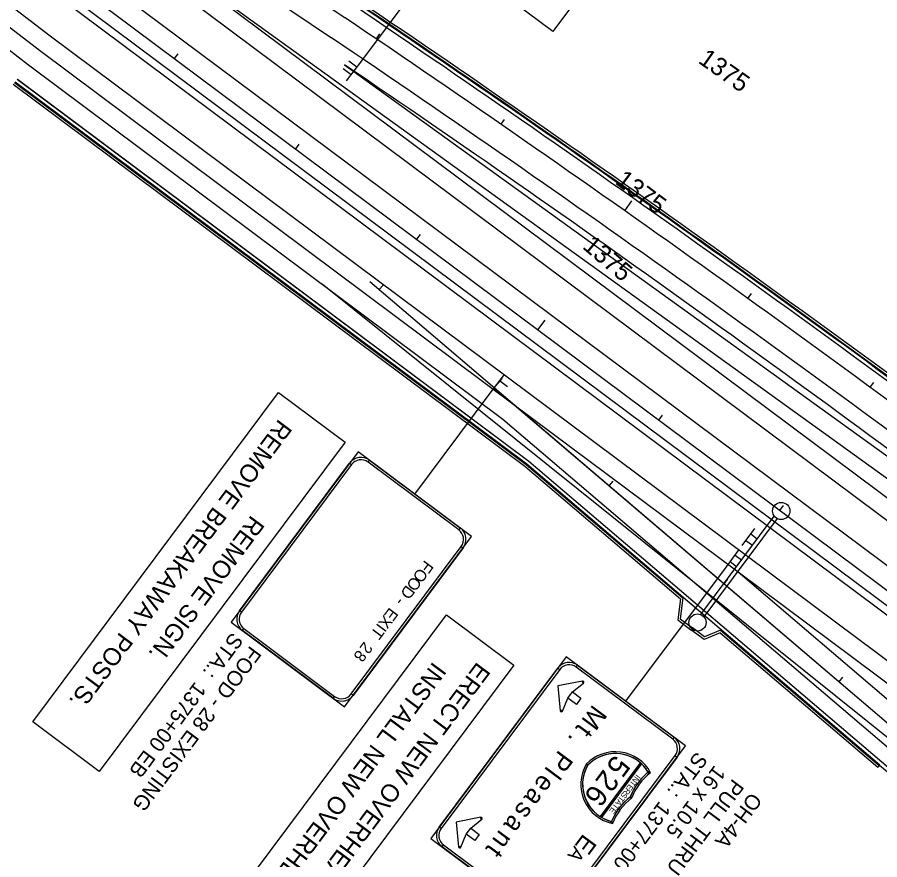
# Model space of a CAD drawing. Extents: x 2338610 to 2351914, y 366540 to 376484.
# Drawn here: x 2344129 to 2344700, y 370808 to 371366 of the extents above; entities that cross this region are included whole.
import ezdxf

# ---------------------------------------------------------------- set-up
doc = ezdxf.new("R2010")
doc.units = 0
for name, color, linetype in [('RD_HC_Cl', 7, 'Continuous'), ('RD_HC_CL_Rel', 7, 'Continuous'), ('RD_PD_Final_LnLine', 7, 'Continuous'), ('RD_PD_Final_TrvlWay', 7, 'Continuous'), ('RD_PD_MedBWall', 7, 'Continuous'), ('RD_PD_MedGR', 7, 'Continuous'), ('RD_PD_NOISE-WALL-GM', 7, 'Continuous'), ('RD_PD_PaveShd', 7, 'Continuous'), ('RD_PD_WallFill', 7, 'Continuous'), ('TR PM UNASSIGNED 3', 7, 'Continuous'), ('TR SN EXISTING - BREAK-AWAY SIGN SUPPORTS', 7, 'Continuous'), ('TR SN EXTRUDED PANEL SIGNS - GROUND MOUNTED', 7, 'Continuous'), ('TR SN EXTRUDED PANEL SIGNS- MOUNTED OVERHEAD', 7, 'Continuous'), ('TR SN UNASSIGNED 7', 7, 'Continuous')]:
    doc.layers.add(name, color=color, linetype=linetype)

msp = doc.modelspace()

# ---------------------------------------------------------------- linework, layer by layer
at = {"layer": 'RD_HC_Cl'}
for p, q in [((2339299.68, 375020.33), (2345298.75, 370542.85)), ((2343974.34, 371616.02), (2344345.74, 371365.34))]:
    msp.add_line(p, q, dxfattribs=at)
msp.add_arc((2338191.84, 362247.8), 11000, 52.99132, 55.982505, dxfattribs=at)
at = {"layer": 'RD_HC_CL_Rel'}
msp.add_line((2344362.05, 371190.8), (2344818.24, 370801.72), dxfattribs=at)
at = {"layer": 'RD_PD_Final_LnLine'}
for p, q in [((2343572.21, 371799.04), (2344150.54, 371353.45)), ((2343565.03, 371789.42), (2344143.36, 371343.83)), ((2344202.18, 371422.64), (2344782.88, 370989.22)), ((2344195, 371413.02), (2345320.98, 370572.63)), ((2344150.54, 371353.45), (2345276.52, 370513.06)), ((2344143.36, 371343.83), (2344457.72, 371109.21)), ((2344330.62, 371189.3), (2344989.66, 370660.63)), ((2344330.62, 371189.3), (2344989.66, 370660.63)), ((2344330.62, 371189.3), (2344989.66, 370660.63)), ((2344330.62, 371189.3), (2344989.66, 370660.63)), ((2344457.72, 371109.21), (2344818.24, 370801.72)), ((2344457.72, 371109.21), (2344605.78, 370998.71))]:
    msp.add_line(p, q, dxfattribs=at)
at = {"layer": 'RD_PD_Final_TrvlWay'}
for p, q in [((2343557.85, 371779.81), (2344136.19, 371334.22)), ((2343974.34, 371616.02), (2344345.74, 371365.34)), ((2343950.18, 371613.02), (2344336.79, 371352.08)), ((2344202.18, 371422.64), (2344790.37, 370998.61)), ((2344136.19, 371334.22), (2344450.23, 371099.83)), ((2344450.23, 371099.83), (2344810.46, 370792.59)), ((2344605.78, 370998.71), (2345269.34, 370503.45)), ((2344605.78, 370998.71), (2344826.03, 370810.85))]:
    msp.add_line(p, q, dxfattribs=at)
for radius in [11000, 10984]:
    msp.add_arc((2338191.84, 362247.8), radius, 52.99132, 55.982505, dxfattribs=at)
at = {"layer": 'RD_PD_MedBWall'}
for p, q in [((2344127.3, 371322.96), (2344466.02, 371070.16)), ((2344128.71, 371324.82), (2344467.41, 371072.03)), ((2344467.41, 371072.03), (2344803.97, 370784.99)), ((2344465.9, 371070.25), (2344699.6, 370870.93))]:
    msp.add_line(p, q, dxfattribs=at)
for radius in [11010, 11012.33]:
    msp.add_arc((2338191.84, 362247.8), radius, 52.99132, 55.982505, dxfattribs=at)
at = {"layer": 'RD_PD_MedGR'}
msp.add_line((2343635.7, 371774.1), (2345204.83, 370602.96), dxfattribs=at)
at = {"layer": 'RD_PD_NOISE-WALL-GM'}
for p, q in [((2344127, 371322.56), (2344465.65, 371069.81)), ((2344126.1, 371321.36), (2344464.71, 371068.64)), ((2344464.71, 371068.64), (2344567.61, 370980.88)), ((2344465.65, 371069.81), (2344569.19, 370981.5)), ((2344567.61, 370980.88), (2344565.95, 370966.87)), ((2344569.19, 370981.5), (2344567.54, 370967.55)), ((2344565.95, 370966.87), (2344574.66, 370960.37)), ((2344567.54, 370967.55), (2344575.56, 370961.57)), ((2344583.37, 370953.87), (2344574.66, 370960.37)), ((2344583.57, 370955.59), (2344575.56, 370961.57)), ((2344593.94, 370958.42), (2344583.37, 370953.87)), ((2344594.2, 370960.16), (2344583.57, 370955.59)), ((2344593.94, 370958.42), (2344698.3, 370869.41)), ((2344594.2, 370960.16), (2344699.28, 370870.55)), ((2344699.28, 370870.55), (2344698.3, 370869.41))]:
    msp.add_line(p, q, dxfattribs=at)
for radius in [11012.83, 11014.33]:
    msp.add_arc((2338191.84, 362247.8), radius, 52.99132, 55.982505, dxfattribs=at)
at = {"layer": 'RD_PD_PaveShd'}
for p, q in [((2343761.92, 371706.31), (2345306.62, 370553.4)), ((2343847.56, 371609.53), (2345290.87, 370532.3)), ((2344345.37, 371334.2), (2344797.47, 371008.28)), ((2344128.79, 371324.76), (2344467.41, 371072.03)), ((2344467.41, 371072.03), (2344803.97, 370784.99))]:
    msp.add_line(p, q, dxfattribs=at)
for radius, end in [(11010, 55.982505), (10974, 55.892847)]:
    msp.add_arc((2338191.84, 362247.8), radius, 52.99132, end, dxfattribs=at)
at = {"layer": 'RD_PD_WallFill'}
msp.add_line((2344699.49, 370870.8), (2344802.34, 370783.08), dxfattribs=at)
at = {"layer": 'TR SN EXISTING - BREAK-AWAY SIGN SUPPORTS'}
for points in [[(2344439.22, 371389.11), (2344601.89, 371607.06), (2344645.9, 371574.21), (2344483.23, 371356.26)], [(2344345.66, 371084.58), (2344182.99, 370866.63), (2344138.98, 370899.48), (2344301.65, 371117.43)]]:
    msp.add_lwpolyline(points, close=True, dxfattribs=at)
at = {"layer": 'TR SN EXTRUDED PANEL SIGNS - GROUND MOUNTED'}
for p, q in [((2344453.43, 371466.7), (2344356.55, 371336.89)), ((2344356.55, 371336.89), (2344346.45, 371323.6)), ((2344348.24, 371336.88), (2344353.53, 371332.86)), ((2344344.35, 371331.77), (2344349.66, 371327.73)), ((2344441.04, 371115.99), (2344451.14, 371129.29)), ((2344453.24, 371121.12), (2344447.93, 371125.16)), ((2344449.35, 371116), (2344444.06, 371120.02)), ((2344391.89, 371050.15), (2344441.04, 371115.99)), ((2344360.91, 371071.33), (2344361.84, 371072.58)), ((2344348.72, 371070.67), (2344349.97, 371069.74)), ((2344421.95, 371027.72), (2344421.01, 371026.47)), ((2344422.6, 371015.53), (2344423.85, 371014.6)), ((2344277.07, 370972.07), (2344275.82, 370973)), ((2344277.73, 370959.88), (2344278.66, 370961.13)), ((2344350.95, 370916.93), (2344349.7, 370917.86)), ((2344338.77, 370916.27), (2344337.83, 370915.02))]:
    msp.add_line(p, q, dxfattribs=at)
for points in [[(2344354.33, 371078.19), (2344270.22, 370965.49), (2344345.35, 370909.41), (2344429.46, 371022.11), (2344354.33, 371078.19), (2344354.33, 371078.19)], [(2344421.01, 371026.47), (2344360.91, 371071.33), (2344361.84, 371072.58), (2344421.95, 371027.72), (2344421.01, 371026.47), (2344421.01, 371026.47)], [(2344349.97, 371069.74), (2344277.07, 370972.07), (2344275.82, 370973), (2344348.72, 371070.67), (2344349.97, 371069.74), (2344349.97, 371069.74)], [(2344349.7, 370917.86), (2344422.6, 371015.53), (2344423.85, 371014.6), (2344350.95, 370916.93), (2344349.7, 370917.86), (2344349.7, 370917.86)], [(2344278.66, 370961.13), (2344338.77, 370916.27), (2344337.83, 370915.02), (2344277.73, 370959.88), (2344278.66, 370961.13), (2344278.66, 370961.13)]]:
    msp.add_lwpolyline(points, close=True, dxfattribs=at)
for centre, radius, start, end in [((2344356.23, 371065.07), 9.38, 53.2636, 143.2638), ((2344356.23, 371065.07), 7.81, 53.2636, 143.2638), ((2344416.34, 371020.21), 7.81, 323.2639, 53.2636), ((2344416.34, 371020.21), 9.38, 323.2639, 53.2636), ((2344283.34, 370967.4), 9.38, 143.2638, 233.264), ((2344283.34, 370967.4), 7.81, 143.2638, 233.264), ((2344343.44, 370922.54), 9.38, 233.2637, 323.2639), ((2344343.44, 370922.54), 7.81, 233.2637, 323.2639)]:
    msp.add_arc(centre, radius, start, end, dxfattribs=at)
at = {"layer": 'TR SN EXTRUDED PANEL SIGNS- MOUNTED OVERHEAD'}
for p, q in [((2344581.13, 370970.44), (2344629.8, 371035.62)), ((2344583.29, 370968.89), (2344631.89, 371033.97)), ((2344608.48, 371016.12), (2344616.9, 371027.39)), ((2344611.01, 371019.5), (2344615.32, 371016.28)), ((2344614.24, 371023.84), (2344618.56, 371020.62)), ((2344598.06, 371002.11), (2344606.47, 371013.38)), ((2344603.82, 371009.82), (2344608.13, 371006.6)), ((2344600.58, 371005.49), (2344604.89, 371002.27)), ((2344531.58, 370913.09), (2344598.06, 371002.11)), ((2344486.52, 370935.02), (2344487.77, 370934.09)), ((2344498.71, 370935.67), (2344499.64, 370936.93)), ((2344502.81, 370926.45), (2344502.95, 370925.68)), ((2344502.95, 370925.68), (2344503.44, 370925.07)), ((2344488.93, 370906.9), (2344488.15, 370906.82)), ((2344489.65, 370906.6), (2344488.93, 370906.9)), ((2344563.5, 370889.26), (2344562.57, 370888.01)), ((2344564.16, 370877.08), (2344565.41, 370876.14)), ((2344505.31, 370871.37), (2344506.16, 370870.57)), ((2344506.32, 370870.79), (2344505.31, 370871.37)), ((2344541.13, 370872.35), (2344514.56, 370836.76)), ((2344515.57, 370836.14), (2344542, 370871.56)), ((2344546.89, 370865.21), (2344547.92, 370865.77)), ((2344547.92, 370865.77), (2344547.21, 370866.71)), ((2344534.26, 370849.35), (2344535.36, 370848.94)), ((2344535.36, 370848.94), (2344534.65, 370849.88)), ((2344435.52, 370836.29), (2344435.66, 370835.53)), ((2344435.66, 370835.53), (2344436.15, 370834.92)), ((2344521.7, 370832.53), (2344522.8, 370832.12)), ((2344522.8, 370832.12), (2344523.04, 370833.26)), ((2344409.27, 370828.9), (2344408.01, 370829.84)), ((2344409.92, 370816.72), (2344410.85, 370817.97)), ((2344421.64, 370816.74), (2344420.86, 370816.66)), ((2344422.36, 370816.45), (2344421.64, 370816.74))]:
    msp.add_line(p, q, dxfattribs=at)
for points in [[(2344457.47, 370937.02), (2344257.69, 370669.33), (2344213.08, 370702.63), (2344412.87, 370970.31)], [(2344492.13, 370942.53), (2344402.41, 370822.32), (2344481.29, 370763.44), (2344571.01, 370883.65), (2344492.13, 370942.53), (2344492.13, 370942.53)], [(2344487.77, 370934.09), (2344409.27, 370828.9), (2344408.01, 370829.84), (2344486.52, 370935.02), (2344487.77, 370934.09), (2344487.77, 370934.09)], [(2344562.57, 370888.01), (2344498.71, 370935.67), (2344499.64, 370936.93), (2344563.5, 370889.26), (2344562.57, 370888.01), (2344562.57, 370888.01)], [(2344486.55, 370923.3), (2344488.15, 370906.82), (2344488.93, 370906.9), (2344489.65, 370906.6), (2344493.17, 370915.19), (2344496.2, 370919.26), (2344503.44, 370925.07), (2344502.95, 370925.68), (2344502.81, 370926.45), (2344486.55, 370923.3), (2344486.55, 370923.3)], [(2344501.84, 370915.06), (2344498.8, 370910.99), (2344493.17, 370915.19), (2344496.2, 370919.26), (2344501.84, 370915.06), (2344501.84, 370915.06)], [(2344485.65, 370771.89), (2344564.16, 370877.08), (2344565.41, 370876.14), (2344486.9, 370770.96), (2344485.65, 370771.89), (2344485.65, 370771.89)], [(2344541.13, 370872.35), (2344514.56, 370836.76), (2344515.5, 370836.05), (2344542.07, 370871.64), (2344541.13, 370872.35), (2344541.13, 370872.35)], [(2344419.26, 370833.14), (2344420.86, 370816.66), (2344421.64, 370816.74), (2344422.36, 370816.45), (2344425.88, 370825.03), (2344428.91, 370829.1), (2344436.15, 370834.92), (2344435.66, 370835.53), (2344435.52, 370836.29), (2344419.26, 370833.14), (2344419.26, 370833.14)], [(2344434.55, 370824.9), (2344431.51, 370820.83), (2344425.88, 370825.03), (2344428.91, 370829.1), (2344434.55, 370824.9), (2344434.55, 370824.9)], [(2344410.85, 370817.97), (2344474.72, 370770.3), (2344473.78, 370769.05), (2344409.92, 370816.72), (2344410.85, 370817.97), (2344410.85, 370817.97)]]:
    msp.add_lwpolyline(points, close=True, dxfattribs=at)
for centre in [(2344634.4, 371038.99), (2344578.98, 370965.16)]:
    msp.add_circle(centre, 5.7, dxfattribs=at)
for centre, radius, start, end in [((2344494.03, 370929.41), 9.38, 53.2636, 143.2638), ((2344494.03, 370929.41), 7.81, 53.2636, 143.2638), ((2344502.95, 370925.68), 0.781, 308.791, 100.2387), ((2344488.93, 370906.9), 0.781, 186.2889, 337.7365), ((2344557.89, 370881.75), 9.38, 323.2639, 53.2636), ((2344557.89, 370881.75), 7.81, 323.2639, 53.2636), ((2344524.58, 370853.09), 26.56, 28.5106, 136.5075), ((2344524.58, 370853.09), 26.56, 28.5106, 136.5075), ((2344524.58, 370853.09), 25.39, 28.5106, 136.5075), ((2344524.57, 370853.1), 25.39, 49.2993, 136.1952), ((2344528.31, 370858.1), 26.56, 150.0201, 258.0169), ((2344528.31, 370858.1), 26.56, 150.0201, 258.0169), ((2344524.58, 370853.09), 25.39, 30.7521, 46.6625), ((2344528.31, 370858.1), 25.39, 150.0201, 258.0169), ((2344528.31, 370858.1), 25.39, 150.3324, 237.2283), ((2344570.49, 370835.82), 38.67, 127.0061, 159.5215), ((2344570.56, 370835.88), 38.67, 128.6671, 159.1496), ((2344570.49, 370835.82), 37.5, 127.0061, 159.5215), ((2344570.49, 370835.82), 37.5, 127.0061, 159.5215), ((2344557.93, 370819), 38.67, 127.0061, 159.5215), ((2344557.9, 370818.91), 38.67, 127.3779, 157.8604), ((2344557.93, 370819), 37.5, 127.0061, 159.5215), ((2344557.93, 370819), 37.5, 127.0061, 159.5215), ((2344435.66, 370835.53), 0.781, 308.791, 100.2387), ((2344528.31, 370858.1), 25.39, 239.8649, 255.7755), ((2344415.53, 370824.23), 9.38, 143.2638, 233.264), ((2344415.53, 370824.23), 7.81, 143.2638, 233.264), ((2344421.64, 370816.74), 0.781, 186.2889, 337.7365)]:
    msp.add_arc(centre, radius, start, end, dxfattribs=at)
at = {"layer": 'TR SN UNASSIGNED 7'}
for p, q in [((2344366.41, 371351.35), (2344368.66, 371354.66)), ((2344232.88, 371338.38), (2344235.27, 371341.58)), ((2344448.92, 371294.85), (2344451.19, 371298.14)), ((2344313.02, 371278.56), (2344315.41, 371281.77)), ((2344530.9, 371237.59), (2344535.51, 371244.13)), ((2344393.16, 371218.75), (2344395.55, 371221.95)), ((2344368.3, 371185.47), (2344370.89, 371188.52)), ((2344612.37, 371179.59), (2344614.7, 371182.84)), ((2344473.3, 371158.94), (2344478.08, 371165.35)), ((2344444.38, 371120.58), (2344449.58, 371126.67)), ((2344693.3, 371120.85), (2344695.66, 371124.08)), ((2344553.44, 371099.12), (2344555.83, 371102.33)), ((2344520.47, 371055.69), (2344523.07, 371058.73)), ((2344633.57, 371039.31), (2344635.97, 371042.51)), ((2344596.56, 370990.8), (2344599.15, 370993.84)), ((2344672.64, 370925.91), (2344675.24, 370928.95))]:
    msp.add_line(p, q, dxfattribs=at)

# ---------------------------------------------------------------- texts
at = {"layer": 'TR PM UNASSIGNED 3'}
for s, p in [('STA.:  1375+00 EB', (2344270.95, 370959.29)), ('FOOD - 28 EXISTING', (2344282.97, 370950.32)), ('STA.:  1377+00 EB', (2344578.33, 370880.26)), ('16 x 10.5', (2344590.35, 370871.29)), ('PULL THRU', (2344602.37, 370862.32)), ('OH-4A', (2344614.39, 370853.35))]:
    msp.add_text(s, height=10, rotation=233.2637, dxfattribs=at).set_placement(p)
at = {"layer": 'TR SN EXISTING - BREAK-AWAY SIGN SUPPORTS'}
for s, p in [('REMOVE BREAKAWAY POSTS.', (2344301.96, 371100.34)), ('REMOVE SIGN.', (2344283.73, 371036.73))]:
    msp.add_text(s, height=11.7187, rotation=233.2638, dxfattribs=at).set_placement(p)
at = {"layer": 'TR SN EXTRUDED PANEL SIGNS - GROUND MOUNTED'}
for s, p in [('F', (2344398.57, 371006.84)), ('O', (2344394.84, 371001.85)), ('O', (2344390.68, 370996.28)), ('D', (2344386.3, 370990.41)), ('-', (2344380.36, 370982.45)), ('E', (2344375.22, 370975.56)), ('X', (2344371.49, 370970.57)), ('I', (2344367.48, 370965.19)), ('T', (2344365.87, 370963.04)), ('2', (2344358.35, 370952.96)), ('8', (2344354.33, 370947.58))]:
    msp.add_text(s, height=7.81, rotation=233.2637, dxfattribs=at).set_placement(p)
at = {"layer": 'TR SN EXTRUDED PANEL SIGNS- MOUNTED OVERHEAD'}
for s, height, rotation, p in [('INSTALL NEW OVERHEAD SIGN(S).', 11.7187, 233.2638, (2344404.08, 370939.78)), ('ERECT NEW OVERHEAD SIGN BRIDGE.', 11.7187, 233.2638, (2344433.21, 370939.62)), ('M', 12.5, 233.2637, (2344509.86, 370911.43)), ('t', 12.5, 233.2637, (2344500.57, 370898.98)), ('.', 12.5, 233.2637, (2344495.27, 370891.89)), ('P', 12.5, 233.2637, (2344487.42, 370881.37)), ('5', 14.06, 233.2637, (2344524.13, 370878.3)), ('l', 12.5, 233.2637, (2344479.37, 370870.58)), ('2', 14.06, 233.2637, (2344516.9, 370868.62)), ('e', 12.5, 233.2637, (2344475.65, 370865.6)), ('T', 3.91, 233.2637, (2344535.61, 370861.04)), ('N', 3.91, 233.2637, (2344537.62, 370863.73)), ('I', 3.91, 233.2637, (2344538.53, 370864.95)), ('a', 12.5, 233.2637, (2344469.06, 370856.76)), ('6', 14.06, 233.2637, (2344509.67, 370858.93)), ('R', 3.91, 233.2637, (2344531.89, 370856.05)), ('E', 3.91, 233.2637, (2344533.75, 370858.54)), ('A', 3.91, 233.2637, (2344526.3, 370848.56)), ('T', 3.91, 233.2637, (2344527.87, 370850.67)), ('S', 3.91, 233.2637, (2344529.88, 370853.36)), ('s', 12.5, 233.2637, (2344462.15, 370847.51)), ('E', 3.91, 233.2637, (2344522.34, 370843.26)), ('T', 3.91, 233.2637, (2344524.2, 370845.75)), ('a', 12.5, 233.2637, (2344455.71, 370838.88)), ('n', 12.5, 233.2637, (2344448.03, 370828.59)), ('E', 11.72, 233.2637, (2344503.54, 370825.9)), ('t', 12.5, 233.2637, (2344441.07, 370819.27)), ('A', 9.37, 233.2637, (2344497.52, 370817.84))]:
    msp.add_text(s, height=height, rotation=rotation, dxfattribs=at).set_placement(p)
at = {"layer": 'TR SN UNASSIGNED 7'}
for rotation, p in [(324.8108, (2344578.81, 371335.96)), (323.2637, (2344523.84, 371255.98)), (319.5396, (2344502.2, 371213.21))]:
    msp.add_text('1375', height=12, rotation=rotation, dxfattribs=at).set_placement(p)

doc.saveas('drawing.dxf')
